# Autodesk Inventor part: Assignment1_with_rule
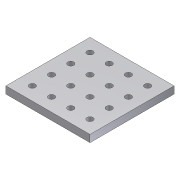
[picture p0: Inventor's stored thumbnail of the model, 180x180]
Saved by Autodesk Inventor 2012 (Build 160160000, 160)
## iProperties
RuleStatus: InUse
Created: 2011-07
Part Number: Assignment1_with_rule
Document SubType Name: Modeling
Designer: asr06799
Density: 1 g/cm^3
Material: Default
Author: asr06799
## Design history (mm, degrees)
sketch "Sketch1"
  geometry: L1 (0, 0)-(700, 0); L2 (700, 0)-(700, -700); L3 (700, -700)-(0, -700); L4 (0, -700)-(0, 0)
  constraints: 8 end point, 2 parallel, 1 horizontal, 1 perpendicular
  dimensions: "Width" = 700 distance of L2.end L3.end; "Length" = 700 distance of L3.end L1.start
extrude "Plate" new body sketch "Sketch1" taper "d2" = 0 deg; distance "d3" = 60
hole "Hole1" diameter "HoleDiameter" = 50; stored, may be unused: countersink angle "d13" = 90 deg, drill point angle "d15" = 118 deg; dims "d4" = 110 (computed from RowSpacing, RowQuantity, Length), "d5" = 110 (computed from ColumnSpacing, ColumnQuantity, Width), "d11" = 4, "d12" = 2, "d14" = 8, "d24" = 6
pattern_linear "Rectangular Pattern1" dims "RowSpacing" = 160
body "Solid1"
